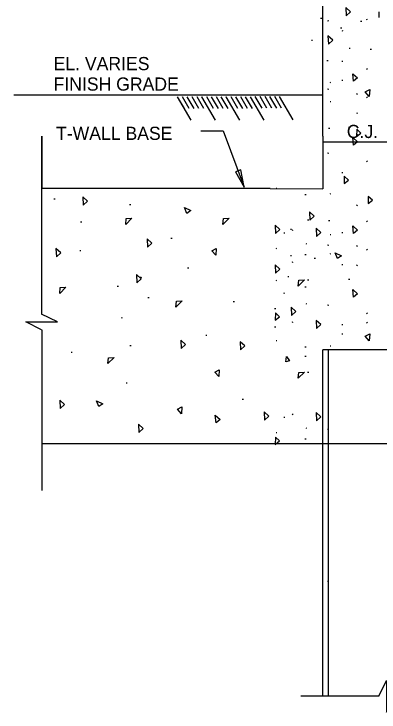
# Model space of a CAD drawing. Extents: x 22388.1 to 22405.7, y 22369.6 to 22390.4.
# Drawn here: x 22395.029 to 22396.329, y 22372.583 to 22375.068 of the extents above; entities that cross this region are included whole.
import ezdxf

# ---------------------------------------------------------------- set-up
doc = ezdxf.new("R2010")
doc.units = 0
for name, color, linetype in [('Level 1', 7, 'Continuous'), ('Level 2', 7, 'Continuous'), ('Level 3', 7, 'Continuous'), ('Level 4', 7, 'Continuous'), ('Level 44', 7, 'Continuous'), ('Level 50', 7, 'Continuous'), ('Level 7', 7, 'Continuous')]:
    doc.layers.add(name, color=color, linetype=linetype)

msp = doc.modelspace()

# ---------------------------------------------------------------- linework, layer by layer
at = {"layer": 'Level 1'}
for p, q in [((22395.6602, 22374.6891), (22395.6118, 22374.7721)), ((22395.636, 22374.7306), (22395.6118, 22374.7721)), ((22395.6533, 22374.7306), (22395.6291, 22374.7722)), ((22395.6706, 22374.7307), (22395.6464, 22374.7723)), ((22395.6879, 22374.7308), (22395.6637, 22374.7723)), ((22395.7052, 22374.7309), (22395.681, 22374.7724)), ((22395.7467, 22374.6894), (22395.6983, 22374.7725)), ((22395.7225, 22374.7309), (22395.6983, 22374.7725)), ((22395.7398, 22374.731), (22395.7156, 22374.7725)), ((22395.7571, 22374.7311), (22395.733, 22374.7726)), ((22395.7744, 22374.7311), (22395.7502, 22374.7727)), ((22395.7917, 22374.7312), (22395.7675, 22374.7727)), ((22395.809, 22374.7313), (22395.7848, 22374.7728)), ((22395.8332, 22374.6897), (22395.7849, 22374.7728)), ((22395.8263, 22374.7313), (22395.8021, 22374.7729)), ((22395.8436, 22374.7314), (22395.8195, 22374.7729)), ((22395.8609, 22374.7315), (22395.8367, 22374.773)), ((22395.8782, 22374.7315), (22395.854, 22374.7731)), ((22395.9198, 22374.6901), (22395.8713, 22374.7731)), ((22395.9128, 22374.7317), (22395.8886, 22374.7732)), ((22395.9301, 22374.7318), (22395.906, 22374.7733)), ((22395.9475, 22374.7318), (22395.9233, 22374.7734)), ((22395.9647, 22374.7319), (22395.9405, 22374.7734)), ((22395.982, 22374.732), (22395.9578, 22374.7735)), ((22396.0236, 22374.6905), (22395.9752, 22374.7736)), ((22396.3281, 22372.6388), (22396.0506, 22372.6388))]:
    msp.add_line(p, q, dxfattribs=at)
for points in [[(22395.1277, 22373.9432), (22395.0714, 22373.9712), (22395.1838, 22373.9712), (22395.1277, 22373.9995)], [(22396.3281, 22372.6388), (22396.356, 22372.695), (22396.356, 22372.5827), (22396.3843, 22372.6388)]]:
    msp.add_lwpolyline(points, dxfattribs=at)
at = {"layer": 'Level 2'}
for p, q in [((22396.3292, 22375.0547), (22396.3292, 22375.0749)), ((22395.6944, 22374.6521), (22395.7742, 22374.6521)), ((22395.7742, 22374.6521), (22395.8494, 22374.4505)), ((22395.1287, 22373.999), (22395.1287, 22374.6326)), ((22395.1287, 22374.6326), (22395.1287, 22374.4456)), ((22396.1287, 22374.6326), (22396.1287, 22374.4456)), ((22396.6287, 22374.6118), (22396.1287, 22374.6118)), ((22395.9418, 22374.4457), (22395.1287, 22374.4457)), ((22395.9418, 22374.4457), (22396.1287, 22374.4456)), ((22395.1287, 22373.9427), (22395.1287, 22373.3711)), ((22396.6287, 22373.8723), (22396.1287, 22373.8723)), ((22396.1287, 22372.6388), (22396.1287, 22373.8723)), ((22396.1495, 22372.6388), (22396.1495, 22373.8723)), ((22397.6287, 22373.5369), (22395.1287, 22373.5369)), ((22396.1287, 22372.6388), (22396.1287, 22373.2368))]:
    msp.add_line(p, q, dxfattribs=at)
msp.add_lwpolyline([(22395.8494, 22374.4505), (22395.8373, 22374.5125), (22395.8179, 22374.5053)], close=True, dxfattribs=at)
at = {"layer": 'Level 3'}
msp.add_line((22396.1287, 22374.7784), (22395.0292, 22374.7784), dxfattribs=at)
at = {"layer": 'Level 44'}
for p, q in [((22396.1211, 22375.0532), (22396.1256, 22375.0532)), ((22396.2841, 22375.0474), (22396.2878, 22375.0496)), ((22396.1457, 22375.0426), (22396.1502, 22375.0438)), ((22396.2635, 22375.0415), (22396.268, 22375.0415)), ((22396.1917, 22375.0179), (22396.1962, 22375.0179)), ((22396.1967, 22375.0084), (22396.2004, 22375.008)), ((22396.0882, 22374.9744), (22396.0927, 22374.9744)), ((22396.2223, 22374.9461), (22396.2268, 22374.9461)), ((22396.2976, 22374.9426), (22396.3021, 22374.9426)), ((22396.1435, 22374.9025), (22396.148, 22374.9025)), ((22396.1967, 22374.9001), (22396.2004, 22374.8998)), ((22396.2841, 22374.8707), (22396.2878, 22374.8729)), ((22396.1547, 22374.8239), (22396.158, 22374.8244)), ((22396.1967, 22374.8317), (22396.2004, 22374.8314)), ((22396.1457, 22374.8006), (22396.1502, 22374.7994)), ((22396.249, 22374.7846), (22396.253, 22374.7826)), ((22396.2841, 22374.7698), (22396.2878, 22374.772)), ((22396.1547, 22374.7554), (22396.158, 22374.756)), ((22396.249, 22374.7162), (22396.253, 22374.7142)), ((22396.1493, 22374.6609), (22396.1538, 22374.6609)), ((22396.2203, 22374.6648), (22396.2248, 22374.6648)), ((22396.1457, 22374.5736), (22396.1502, 22374.5724)), ((22396.2841, 22374.5428), (22396.2878, 22374.545)), ((22396.1967, 22374.5038), (22396.2004, 22374.5034)), ((22395.9624, 22374.447), (22395.9657, 22374.4473)), ((22396.065, 22374.4247), (22396.0695, 22374.4247)), ((22396.1547, 22374.4275), (22396.158, 22374.4281)), ((22395.171, 22374.4099), (22395.1755, 22374.4099)), ((22395.4409, 22374.3894), (22395.4454, 22374.3894)), ((22396.249, 22374.3883), (22396.253, 22374.3863)), ((22395.2667, 22374.3279), (22395.2712, 22374.3279)), ((22396.0747, 22374.3345), (22396.0789, 22374.3345)), ((22396.1493, 22374.3329), (22396.1538, 22374.3329)), ((22396.2841, 22374.329), (22396.2878, 22374.3313)), ((22396.0134, 22374.302), (22396.0179, 22374.302)), ((22396.02, 22374.298), (22396.0236, 22374.2997)), ((22395.9898, 22374.2879), (22395.9942, 22374.2887)), ((22396.1547, 22374.2822), (22396.158, 22374.2828)), ((22396.1967, 22374.29), (22396.2004, 22374.2897)), ((22395.5878, 22374.2698), (22395.5923, 22374.2698)), ((22396.0681, 22374.2502), (22396.0713, 22374.2489)), ((22395.2633, 22374.2254), (22395.2678, 22374.2254)), ((22395.9624, 22374.2333), (22395.9657, 22374.2335)), ((22396.1457, 22374.2457), (22396.1502, 22374.2444)), ((22396.249, 22374.2429), (22396.253, 22374.2409)), ((22396.2841, 22374.2281), (22396.2878, 22374.2304)), ((22396.0134, 22374.2078), (22396.0179, 22374.2078)), ((22396.065, 22374.2109), (22396.0695, 22374.2109)), ((22396.1547, 22374.2138), (22396.158, 22374.2144)), ((22396.02, 22374.1839), (22396.0236, 22374.1855)), ((22396.098, 22374.1984), (22396.1025, 22374.1984)), ((22396.1967, 22374.1759), (22396.2004, 22374.1755)), ((22395.647, 22374.1639), (22395.6515, 22374.1639)), ((22396.249, 22374.1745), (22396.253, 22374.1725)), ((22395.479, 22374.1318), (22395.483, 22374.1298)), ((22396.004, 22374.1325), (22396.0085, 22374.1325)), ((22395.9624, 22374.1191), (22395.9657, 22374.1194)), ((22396.0747, 22374.1208), (22396.0789, 22374.1208)), ((22396.2203, 22374.1231), (22396.2248, 22374.1231)), ((22395.3965, 22374.099), (22395.401, 22374.099)), ((22396.065, 22374.0968), (22396.0695, 22374.0968)), ((22395.5058, 22374.058), (22395.5103, 22374.058)), ((22395.9898, 22374.0742), (22395.9942, 22374.0749)), ((22395.8099, 22374.0444), (22395.8144, 22374.0444)), ((22396.0681, 22374.0364), (22396.0713, 22374.0352)), ((22396.1457, 22374.0319), (22396.1502, 22374.0307)), ((22395.9569, 22374.0195), (22395.9614, 22374.0195)), ((22396.2841, 22374.0011), (22396.2878, 22374.0034)), ((22395.411, 22373.9866), (22395.4147, 22373.9863)), ((22395.9569, 22373.9536), (22395.9614, 22373.9536)), ((22396.02, 22373.9701), (22396.0236, 22373.9718)), ((22396.1967, 22373.9621), (22396.2004, 22373.9618)), ((22396.2841, 22373.9679), (22396.2878, 22373.9702)), ((22396.1967, 22373.9289), (22396.2004, 22373.9286)), ((22395.7119, 22373.9248), (22395.7164, 22373.9248)), ((22395.9624, 22373.9054), (22395.9657, 22373.9056)), ((22395.442, 22373.8872), (22395.4465, 22373.8872)), ((22396.065, 22373.883), (22396.0695, 22373.883)), ((22396.1547, 22373.8859), (22396.158, 22373.8864)), ((22395.2325, 22373.8633), (22395.237, 22373.8633)), ((22396.065, 22373.8498), (22396.0695, 22373.8498)), ((22396.0747, 22373.7929), (22396.0789, 22373.7929)), ((22395.4284, 22373.754), (22395.4326, 22373.754)), ((22395.8417, 22373.6959), (22395.846, 22373.6959)), ((22395.9898, 22373.6321), (22395.9942, 22373.6329)), ((22396.02, 22373.6422), (22396.0236, 22373.6439)), ((22396.0681, 22373.5944), (22396.0713, 22373.5931)), ((22396.1457, 22373.5899), (22396.1502, 22373.5886)), ((22395.9624, 22373.5774), (22395.9657, 22373.5777)), ((22396.065, 22373.5551), (22396.0695, 22373.5551)), ((22396.1457, 22373.0482), (22396.1502, 22373.0469))]:
    msp.add_line(p, q, dxfattribs=at)
for points in [[(22396.2123, 22375.0611), (22396.2277, 22375.0754), (22396.2106, 22375.0906)], [(22396.1487, 22374.9598), (22396.1642, 22374.9741), (22396.1471, 22374.9893)], [(22396.2355, 22374.8549), (22396.2526, 22374.8399), (22396.2384, 22374.828)], [(22396.2942, 22374.7738), (22396.28, 22374.7898), (22396.2959, 22374.7983)], [(22396.2489, 22374.6317), (22396.2649, 22374.6438), (22396.2496, 22374.6574)], [(22396.2355, 22374.6279), (22396.2526, 22374.6129), (22396.2384, 22374.601)], [(22396.2045, 22374.4643), (22396.2205, 22374.4764), (22396.2051, 22374.49)], [(22395.2759, 22374.3874), (22395.2913, 22374.4017), (22395.2742, 22374.4169)], [(22396.2899, 22374.3926), (22396.3059, 22374.4047), (22396.2906, 22374.4182)], [(22395.6445, 22374.3578), (22395.6365, 22374.3783), (22395.6586, 22374.3675)], [(22396.0832, 22374.3334), (22396.0987, 22374.3477), (22396.0816, 22374.3629)], [(22395.4288, 22374.3393), (22395.4488, 22374.3404), (22395.4271, 22374.3182)], [(22395.7752, 22374.3393), (22395.7952, 22374.3404), (22395.7735, 22374.3182)], [(22395.961, 22374.2864), (22395.9764, 22374.3006), (22395.9593, 22374.3159)], [(22396.1067, 22374.2754), (22396.1221, 22374.2896), (22396.105, 22374.3049)], [(22396.2355, 22374.3132), (22396.2526, 22374.2983), (22396.2384, 22374.2864)], [(22395.5048, 22374.2371), (22395.5202, 22374.2513), (22395.5031, 22374.2666)], [(22395.1802, 22374.2029), (22395.1956, 22374.2172), (22395.1786, 22374.2324)], [(22395.7481, 22374.2084), (22395.7339, 22374.2244), (22395.7498, 22374.2329)], [(22396.1808, 22374.1974), (22396.1729, 22374.2178), (22396.195, 22374.207)], [(22395.961, 22374.1451), (22395.9764, 22374.1594), (22395.9593, 22374.1746)], [(22395.4672, 22374.1107), (22395.4826, 22374.1249), (22395.4655, 22374.1402)], [(22396.0434, 22374.1197), (22396.0634, 22374.1208), (22396.0417, 22374.0986)], [(22395.1942, 22374.0935), (22395.2142, 22374.0945), (22395.1925, 22374.0724)], [(22396.2355, 22374.0862), (22396.2526, 22374.0713), (22396.2384, 22374.0594)], [(22395.6076, 22374.045), (22395.6276, 22374.0461), (22395.6059, 22374.024)], [(22395.9592, 22373.9775), (22395.9752, 22373.9896), (22395.9599, 22374.0032)], [(22396.0174, 22373.9945), (22396.0328, 22374.0087), (22396.0157, 22374.024)], [(22396.1067, 22373.9474), (22396.1221, 22373.9617), (22396.105, 22373.9769)], [(22396.2942, 22373.9042), (22396.28, 22373.9202), (22396.2959, 22373.9287)], [(22395.6251, 22373.8765), (22395.6405, 22373.8907), (22395.6235, 22373.906)], [(22395.8362, 22373.8715), (22395.8516, 22373.8858), (22395.8345, 22373.901)], [(22395.3655, 22373.8439), (22395.3855, 22373.845), (22395.3638, 22373.8228)], [(22395.9977, 22373.8297), (22396, 22373.8479), (22396.0102, 22373.8327)], [(22395.7585, 22373.7768), (22395.7443, 22373.7928), (22395.7602, 22373.8013)], [(22396.0434, 22373.7918), (22396.0634, 22373.7929), (22396.0417, 22373.7707)], [(22395.1939, 22373.6631), (22395.2093, 22373.6774), (22395.1922, 22373.6926)], [(22395.3311, 22373.6698), (22395.3232, 22373.6902), (22395.3453, 22373.6794)], [(22395.6255, 22373.6443), (22395.6113, 22373.6603), (22395.6272, 22373.6688)], [(22395.7461, 22373.6391), (22395.7632, 22373.6241), (22395.749, 22373.6122)], [(22395.9216, 22373.6221), (22395.937, 22373.6364), (22395.9199, 22373.6516)], [(22396.1067, 22373.6195), (22396.1221, 22373.6338), (22396.105, 22373.649)], [(22395.474, 22373.5777), (22395.4895, 22373.592), (22395.4724, 22373.6072)], [(22395.9592, 22373.5354), (22395.9752, 22373.5475), (22395.9599, 22373.5611)]]:
    msp.add_lwpolyline(points, close=True, dxfattribs=at)
at = {"layer": 'Level 50'}
for p, q in [((22395.8433, 22374.4667), (22395.8433, 22374.4667)), ((22395.8494, 22374.4505), (22395.8494, 22374.4505))]:
    msp.add_line(p, q, dxfattribs=at)
at = {"layer": 'Level 7'}
msp.add_line((22396.1287, 22374.6326), (22396.1287, 22376.2749), dxfattribs=at)

# ---------------------------------------------------------------- texts
at = {"layer": 'Level 2'}
msp.add_text('T-WALL BASE', height=0.046875, dxfattribs=at).set_placement((22395.179, 22374.6193))
at = {"layer": 'Level 4'}
for s, height, p in [('EL. VARIES', 0.04688, (22395.1704, 22374.8675)), ('FINISH GRADE', 0.046875, (22395.1704, 22374.7946))]:
    msp.add_text(s, height=height, rotation=360, dxfattribs=at).set_placement(p)
msp.add_text('C.J.', height=0.04688, dxfattribs=at).set_placement((22396.2144, 22374.6259))

doc.saveas('drawing.dxf')
